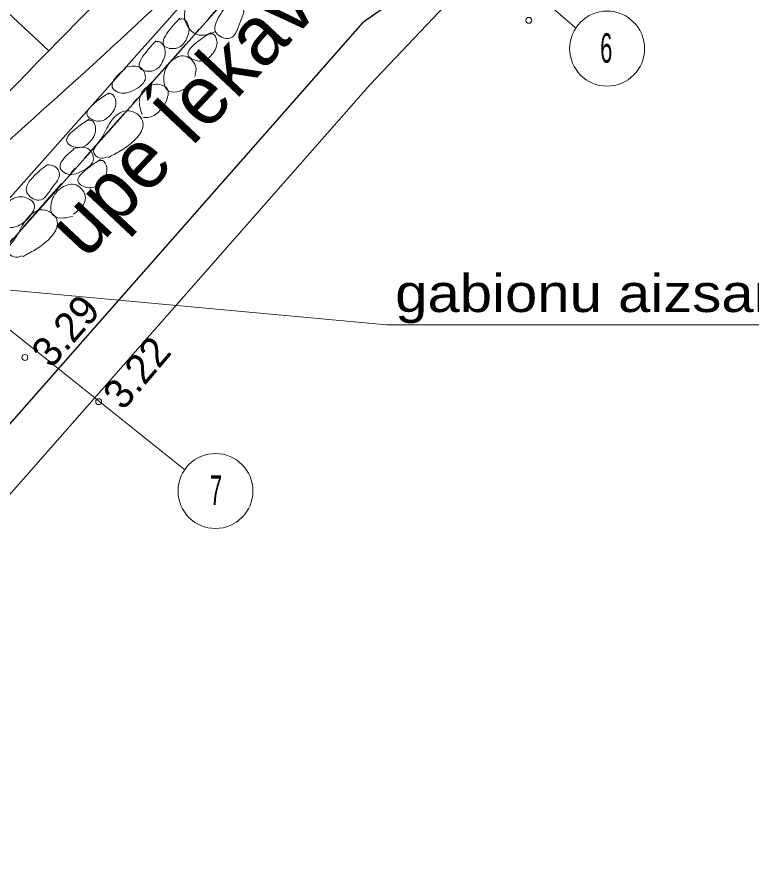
# Model space of a CAD drawing. Extents: x -1320 to -1174, y 762 to 862.
# Drawn here: x -1244.99 to -1232.55, y 797.2 to 811.79 of the extents above; entities that cross this region are included whole.
import ezdxf
from ezdxf.enums import TextEntityAlignment as Align

# ---------------------------------------------------------------- set-up
doc = ezdxf.new("R2010")
doc.units = 0
doc.header["$LTSCALE"] = 0.2
doc.linetypes.add('DOT_DASHED', pattern=[7.7, 5, -1.2, 0.3, -1.2])
for name, color, linetype, lineweight in [('1', 7, 'Continuous', 13), ('19', 7, 'Continuous', 25), ('55', 7, 'Continuous', 13), ('6', 7, 'Continuous', 13), ('62', 7, 'Continuous', 13), ('63', 7, 'Continuous', 13)]:
    doc.layers.add(name, color=color, linetype=linetype, lineweight=lineweight)
doc.layers.add('27', color=7, linetype='Continuous')
doc.layers.add('8', color=7, linetype='Continuous')

msp = doc.modelspace()

# ---------------------------------------------------------------- linework, layer by layer
at = {"layer": '1'}
for p, q in [((-1247.111, 821.685), (-1235.538, 811.611)), ((-1256.057, 815.213), (-1242.15, 804.124)), ((-1247.751, 814.276), (-1244.455, 811.216))]:
    msp.add_line(p, q, dxfattribs=at)
for centre in [(-1234.9969, 811.255), (-1241.633, 803.7645)]:
    msp.add_circle(centre, 0.635, dxfattribs=at)
msp.add_spline([(-1235.8, 825.801), (-1237.913, 825.174), (-1239.203, 823.346), (-1241.709, 821.268), (-1246.557, 815.58), (-1256.526, 805.053), (-1260.592, 799.147), (-1261.416, 795.29), (-1262.742, 791.444), (-1262.206, 785.139)], degree=3, dxfattribs=at)
at = {"layer": '19', "lineweight": 13}
msp.add_spline([(-1253.457, 785.393), (-1253.726, 794.104), (-1251.637, 801.373), (-1250.122, 804.26), (-1247.608, 807.348), (-1239.437, 815.545), (-1236.508, 819.221), (-1228.799, 821.851), (-1223.357, 826.161), (-1220.079, 827.95)], degree=3, dxfattribs=at)
at = {"layer": '55'}
msp.add_lwpolyline([(-1251.178, 781.943), (-1250.876, 788.586), (-1249.424, 796.058), (-1246.365, 802.296), (-1239.008, 810.653), (-1237.317, 812.435), (-1234.783, 813.781), (-1227.269, 819.96), (-1220.231, 823.644), (-1218.172, 824.289), (-1214.858, 828.794), (-1213.694, 830.71)], dxfattribs=at)
at = {"layer": '6'}
for centre in [(-1236.323, 811.7341), (-1244.862, 806.0262), (-1243.613, 805.2772)]:
    msp.add_circle(centre, 0.05, dxfattribs=at)
at = {"layer": '62'}
msp.add_spline([(-1254.434, 786.21), (-1255.853, 794.247), (-1253.373, 799.783), (-1252.196, 801.907), (-1252.103, 801.965), (-1250.675, 804.058), (-1247.791, 807.511), (-1245.419, 810.213), (-1244.186, 811.494), (-1242.939, 812.764), (-1240.149, 815.75), (-1236.129, 820.169), (-1233.075, 822.242), (-1235.394, 825.816)], degree=3, dxfattribs=at)
at = {"layer": '63', "lineweight": 25}
msp.add_lwpolyline([(-1251.428, 785.238), (-1264.287, 784.95), (-1270.386, 788.761), (-1278.142, 789.522), (-1278.429, 820.376), (-1260.692, 834.371), (-1258.181, 840.695), (-1250.014, 845.483), (-1229.719, 840.992), (-1227.821, 835.408), (-1218.992, 825.806), (-1239.144, 811.691), (-1246.246, 803.626), (-1250.024, 795.415), (-1251.371, 785.665)], close=True, dxfattribs=at)
at = {"layer": '63', "linetype": 'DOT_DASHED', "lineweight": 25}
msp.add_lwpolyline([(-1254.918, 786.26), (-1254.605, 794.542), (-1253.865, 797.042), (-1252.437, 799.553), (-1250.698, 801.658), (-1245.95, 807.041), (-1239.139, 814.697), (-1235.363, 819.429), (-1232.239, 822.444), (-1231.619, 822.931), (-1231.44, 822.991), (-1229.31, 823.677), (-1223.125, 826.536)], dxfattribs=at)
at = {"layer": '63', "lineweight": 35}
msp.add_lwpolyline([(-1254.918, 786.26), (-1254.605, 794.542), (-1253.865, 797.042), (-1252.437, 799.553), (-1251.568, 800.606), (-1250.698, 801.658), (-1248.324, 804.35), (-1245.95, 807.041), (-1242.544, 810.869), (-1239.139, 814.697), (-1237.251, 817.063), (-1235.363, 819.429), (-1233.801, 820.936), (-1232.239, 822.444), (-1231.619, 822.931), (-1229.31, 823.677), (-1223.125, 826.536)], dxfattribs=at)
at = {"layer": '63'}
for points in [[(-1231.863, 823.367), (-1235.734, 819.766), (-1239.521, 815.019), (-1242.918, 811.201), (-1245.916, 807.839), (-1248.699, 804.681), (-1251.078, 801.983), (-1252.85, 799.838), (-1253.787, 798.196), (-1254.328, 797.239), (-1254.328, 797.239), (-1255.102, 794.624)], [(-1228.737, 806.576), (-1238.728, 806.576), (-1246.038, 807.247)]]:
    msp.add_lwpolyline(points, dxfattribs=at)
for points in [[(-1241.543, 812.004), (-1241.719, 812.242), (-1242.025, 812.125), (-1242.144, 811.724), (-1241.945, 811.492), (-1241.633, 811.545)], [(-1241.397, 812.046), (-1241.565, 811.813), (-1241.623, 811.521), (-1241.388, 811.433), (-1241.209, 811.721), (-1241.155, 811.935), (-1241.269, 812.058), (-1241.397, 812.046)], [(-1242.238, 811.769), (-1242.406, 811.579), (-1242.511, 811.31), (-1242.276, 811.267), (-1242.124, 811.417), (-1242.1, 811.666), (-1242.201, 811.761), (-1242.258, 811.746)], [(-1241.719, 811.522), (-1241.928, 811.379), (-1242.096, 811.144), (-1241.878, 811.044), (-1241.694, 811.153), (-1241.61, 811.388), (-1241.685, 811.505), (-1241.744, 811.505)], [(-1242.643, 811.386), (-1242.81, 811.196), (-1242.916, 810.927), (-1242.68, 810.884), (-1242.528, 811.035), (-1242.504, 811.283), (-1242.606, 811.378), (-1242.663, 811.364)], [(-1241.984, 810.782), (-1241.969, 810.958), (-1242.178, 811.133), (-1242.397, 811.029), (-1242.508, 810.787), (-1242.423, 810.536), (-1242.24, 810.537), (-1242.101, 810.604)], [(-1243.168, 810.937), (-1242.89, 810.922), (-1242.82, 810.761), (-1243.015, 810.553), (-1243.289, 810.517), (-1243.381, 810.601), (-1243.287, 810.806), (-1243.153, 810.924)], [(-1242.875, 810.14), (-1242.922, 810.389), (-1242.811, 810.592), (-1242.576, 810.646), (-1242.453, 810.578), (-1242.477, 810.348), (-1242.579, 810.2), (-1242.781, 810.088), (-1242.862, 810.093)], [(-1243.432, 810.507), (-1243.641, 810.364), (-1243.809, 810.129), (-1243.591, 810.029), (-1243.407, 810.138), (-1243.323, 810.373), (-1243.398, 810.49), (-1243.457, 810.49)], [(-1243.464, 809.422), (-1243.602, 809.404), (-1243.693, 809.489), (-1243.587, 809.705), (-1243.434, 809.977), (-1243.102, 810.204), (-1242.87, 810.035), (-1243.13, 809.598), (-1243.352, 809.464), (-1243.451, 809.409)], [(-1243.775, 810.058), (-1243.984, 809.915), (-1244.152, 809.68), (-1243.934, 809.58), (-1243.75, 809.689), (-1243.666, 809.924), (-1243.741, 810.041), (-1243.8, 810.041)], [(-1244.049, 809.563), (-1243.771, 809.548), (-1243.701, 809.387), (-1243.896, 809.179), (-1244.17, 809.143), (-1244.262, 809.227), (-1244.168, 809.432), (-1244.034, 809.55)], [(-1243.584, 809.377), (-1243.793, 809.234), (-1243.961, 808.999), (-1243.743, 808.899), (-1243.559, 809.008), (-1243.475, 809.243), (-1243.55, 809.36), (-1243.609, 809.36)], [(-1244.486, 809.285), (-1244.706, 809.1), (-1244.833, 808.831), (-1244.627, 808.688), (-1244.383, 808.924), (-1244.278, 809.118), (-1244.359, 809.265), (-1244.486, 809.285)], [(-1244.039, 808.449), (-1243.836, 808.728), (-1243.996, 808.949), (-1244.234, 808.902), (-1244.401, 808.695), (-1244.38, 808.43), (-1244.202, 808.387), (-1244.051, 808.418)], [(-1245.224, 808.299), (-1245.208, 808.552), (-1245.051, 808.722), (-1244.81, 808.717), (-1244.707, 808.621), (-1244.787, 808.404), (-1244.922, 808.285), (-1245.145, 808.226), (-1245.222, 808.25)], [(-1244.913, 807.745), (-1245.051, 807.727), (-1245.142, 807.812), (-1245.036, 808.028), (-1244.883, 808.3), (-1244.551, 808.527), (-1244.319, 808.358), (-1244.579, 807.921), (-1244.801, 807.787), (-1244.9, 807.732)]]:
    msp.add_spline(points, degree=3, dxfattribs=at)

# ---------------------------------------------------------------- texts
at = {"layer": '1', "width": 0.55}
for s, p in [('6', (-1235.114, 811.016)), ('7', (-1241.728, 803.527))]:
    msp.add_text(s, height=0.5, dxfattribs=at).set_placement(p)
at = {"layer": '27'}
msp.add_text('upe Íekava', height=1, rotation=46.796, dxfattribs=at).set_placement((-1243.835, 807.665))
at = {"layer": '63', "width": 1.15}
msp.add_text('gabionu aizsargsiena', height=0.64, dxfattribs=at).set_placement((-1233.9375, 806.795), align=Align.CENTER)
at = {"layer": '8'}
for s, rotation, p in [(' 3.29', 48.826, (-1244.537, 805.685)), (' 3.22', 49.772, (-1243.317, 804.969))]:
    msp.add_text(s, height=0.5, rotation=rotation, dxfattribs=at).set_placement(p)

doc.saveas('drawing.dxf')
